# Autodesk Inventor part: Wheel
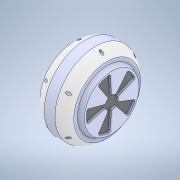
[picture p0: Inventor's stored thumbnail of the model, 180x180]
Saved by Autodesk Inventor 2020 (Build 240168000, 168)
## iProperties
Created: 2020-04
Part Number: Wheel
Material: Générique
Document SubType Name: Modeling
Designer: bruno
Density: 1 g/cm^3
Appearance: Par défaut
Mass: 1294.26 g
Surface Area: 715.733 cm^2
Volume: 1294.26 cm^3
Sending System: SolidWorks 2017
Last Author: hpras
Last Saved: 2020-04-23
Author: bruno
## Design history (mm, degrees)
feature "CirPattern2"
sketch "Esquisse1"
  geometry: C1 r 12.7 at (0, 0); A1 r 12.7 centre (0, 0) between (6.917, -10.651) and (11.413, -5.57) reference; A2 r 12.7 centre (0, 0) between (-7.992, -9.87) and (0.665, -12.683) reference; A3 r 12.7 centre (0, 0) between (-11.856, 4.551) and (-11.856, -4.551) reference; A4 r 12.7 centre (0, 0) between (0.665, 12.683) and (-7.992, 9.87) reference; A5 r 12.7 centre (0, 0) between (11.413, 5.57) and (6.917, 10.651) reference; 11 further points
  constraints: 1 centre point, 1 coincident, 1 concentric
extrude "Extrusion1" join sketch "Esquisse1" distance "d0" = 10; taper "d1" = 0 deg
chamfer "Chanfrein1" distance "d2" = 0.5; stored, may be unused: second distance "d3" = 2, angle "d4" = 45 deg
sketch "Esquisse2"
  geometry: L1 (15.777, 80)-(-33.547, 80); L2 (-33.547, 80)-(-33.547, 89.418); L3 (-33.547, 89.418)-(15.777, 89.418); L4 (15.777, 89.418)-(15.777, 80); L5 (0, 0)-(49.987, 0)
  constraints: 10 end point, 2 horizontal, 2 parallel, 1 perpendicular
  dimensions: "d5" = 80 distance from line of L1 L5.start
revolve "Révolution1" sketch "Esquisse2" stored, may be unused: angle "d6" = 90 deg
sketch "Esquisse3"
  geometry: L1 (0, 0)-(0, 75); C1 r 2.5 at (0, 75)
  constraints: 2 end point, 1 centre point, 1 coincident, 1 vertical
  dimensions: "d7" = 75 distance of L1.start L1.end; "d8" = 5 diameter of C1
extrude "Extrusion2" cut sketch "Esquisse3" distance "d9" = 100; taper "d10" = 0 deg
pattern_circular "Réseau circulaire1" dims angle "d12" = 360 deg
node "Solide1"
